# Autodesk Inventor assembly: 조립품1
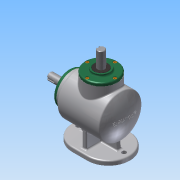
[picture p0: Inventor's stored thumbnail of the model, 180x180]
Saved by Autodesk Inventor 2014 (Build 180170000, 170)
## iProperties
Created: 2016-04
Part Number: 조립품1
Document SubType Name: Assembly
Designer: 703-04
Author: 703-04
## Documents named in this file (14)
- C:\Users\601-\Desktop\460408v1015\조립품1.iam
- C:\Users\601-\Desktop\460408v1015\본체.ipt
- C:\Users\601-\Desktop\460408v1015\서브 축.ipt
- 서브 축.ipt
- C:\Users\601-\Desktop\460408v1015\메인 축.ipt
- 메인 축.ipt
- C:\Users\601-\Desktop\460408v1015\베어링 6203.ipt
- C:\Users\601-\Desktop\460408v1015\키 4x4.ipt
- C:\Users\601-\Desktop\460408v1015\서브 베벨기어.ipt
- C:\Users\601-\Desktop\460408v1015\커버.ipt
- C:\Users\601-\Desktop\460408v1015\오일실 17 32 8.ipt
- C:\Users\601-\Desktop\460408v1015\키 5x5.ipt
- C:\Users\601-\Desktop\460408v1015\메인 베벨기어.ipt
- C:\Users\601-\Desktop\460408v1015\M4.ipt
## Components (8 placed, 1 different names)
1. M4:1
2. M4:2
3. M4:3
4. M4:4
5. M4:5
6. M4:6
7. M4:7
8. M4:8
